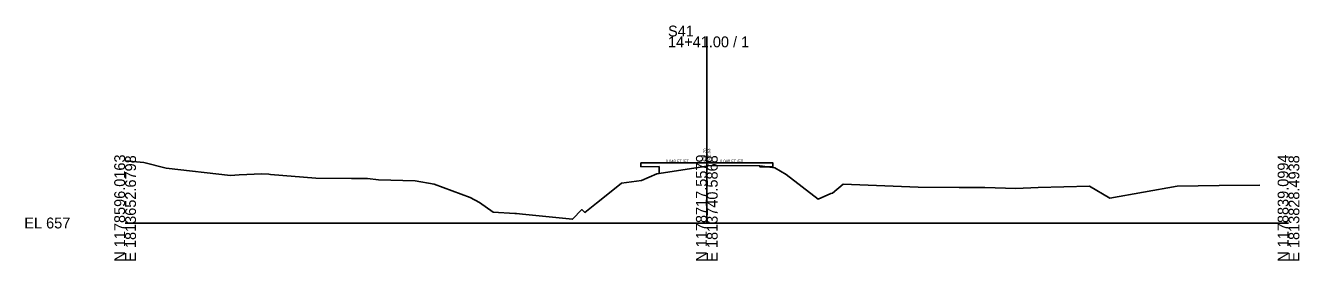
# Model space of a CAD drawing. Extents: x -26 to 6803, y -10 to 6540.
# Drawn here: x 2574.3 to 2902.8, y -9.7 to 51 of the extents above; entities that cross this region are included whole.
import ezdxf

# ---------------------------------------------------------------- set-up
doc = ezdxf.new("R2010")
doc.units = 0
for name, color, linetype in [('Default', 7, 'Continuous'), ('RD_GPK_XS_Cell', 7, 'Continuous'), ('RD_XS_Base', 7, 'Continuous'), ('RD_XS_ExGround', 7, 'Continuous'), ('RD_XS_Misc_Line', 7, 'Continuous'), ('RD_XS_Pave', 7, 'Continuous'), ('RD_XS_TX_Elev_EX', 7, 'Continuous'), ('RD_XS_TX_Slope', 7, 'Continuous')]:
    doc.layers.add(name, color=color, linetype=linetype)

msp = doc.modelspace()

# ---------------------------------------------------------------- linework, layer by layer
at = {"layer": 'Default'}
for q in [(2733, 15.52), (2767, 15.54)]:
    msp.add_line((2750, 15.53), q, dxfattribs=at)
at = {"layer": 'RD_GPK_XS_Cell'}
for p, q in [((2750, 0), (2750, 48.17)), ((2600, 0), (2750, 0)), ((2750, 0), (2900, 0))]:
    msp.add_line(p, q, dxfattribs=at)
at = {"layer": 'RD_XS_Base'}
for p, q in [((2733, 14.52), (2737.73, 14.62)), ((2737.73, 14.62), (2737.73, 12.78)), ((2763.64, 14.76), (2763.64, 14.54)), ((2763.64, 14.54), (2767, 14.54))]:
    msp.add_line(p, q, dxfattribs=at)
at = {"layer": 'RD_XS_ExGround'}
msp.add_lwpolyline([(2600, 16.06), (2604.81, 15.64), (2610.62, 14.13), (2627.16, 12.25), (2629.43, 12.41), (2635.22, 12.74), (2637.09, 12.59), (2637.45, 12.55), (2649.15, 11.62), (2658.4, 11.49), (2662.49, 11.45), (2665.31, 11.14), (2674.79, 10.91), (2679.68, 10.02), (2689.01, 6.59), (2691.41, 5.26), (2694.89, 2.77), (2700.52, 2.43), (2700.91, 2.42), (2702.44, 2.28), (2715.38, 0.97), (2717.8, 3.45), (2718.52, 2.75), (2721.55, 5.14), (2723.64, 6.79), (2728.04, 10.33), (2733.19, 10.97), (2737.08, 12.68), (2750, 14.7), (2750.56, 14.89), (2763.65, 14.76), (2766.9, 14.33), (2767.57, 14.26), (2770.47, 12.49), (2778.71, 6.12), (2782, 7.6), (2782.43, 7.71), (2785.15, 10.02), (2804.51, 9.28), (2815.06, 9.16), (2821.73, 9.14), (2829.68, 8.95), (2835.48, 9.17), (2848.71, 9.51), (2853.9, 6.43), (2871.32, 9.55), (2882.15, 9.65), (2892.57, 9.79)], dxfattribs=at)
at = {"layer": 'RD_XS_Misc_Line'}
for points in [[(2737.73, 14.62), (2737.73, 12.78), (2750, 14.7), (2750.56, 14.89), (2763.64, 14.76), (2765.32, 14.54), (2767, 14.54), (2767, 15.54), (2750, 15.53), (2733, 15.52), (2733, 14.52)], [(2763.64, 14.76), (2763.64, 14.54), (2765.32, 14.54)]]:
    msp.add_lwpolyline(points, close=True, dxfattribs=at)
at = {"layer": 'RD_XS_Pave'}
for p, q in [((2733, 14.52), (2733, 15.52)), ((2767, 14.54), (2767, 15.54))]:
    msp.add_line(p, q, dxfattribs=at)

# ---------------------------------------------------------------- texts
at = {"layer": 'Default'}
msp.add_text(' 672.53', height=0.8, rotation=90, dxfattribs=at).set_placement((2750.88, 15.53))
at = {"layer": 'RD_GPK_XS_Cell'}
for s, p in [('S41', (2740, 48.17)), ('14+41.00 / 1', (2740, 45.37)), ('EL 657', (2574, -1.4))]:
    msp.add_text(s, height=2.8, dxfattribs=at).set_placement(p)
for s, p in [('N 1178596.0163', (2600, -10)), ('E 1813652.6798', (2602.8, -10)), ('N 1178717.5579', (2750, -10)), ('E 1813740.5868', (2752.8, -10)), ('N 1178839.0994', (2900, -10)), ('E 1813828.4938', (2902.8, -10))]:
    msp.add_text(s, height=2.8, rotation=90, dxfattribs=at).set_placement(p)
at = {"layer": 'RD_XS_TX_Elev_EX'}
msp.add_text('671.70', height=0.8, rotation=90, dxfattribs=at).set_placement((2749.89, 15.85))
at = {"layer": 'RD_XS_TX_Slope'}
for p in [(2739.4, 15.61), (2753.41, 15.62)]:
    msp.add_text('0.048 FT./FT.', height=0.75, rotation=0.0293, dxfattribs=at).set_placement(p)

doc.saveas('drawing.dxf')
